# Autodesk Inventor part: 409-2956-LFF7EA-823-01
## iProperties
Created: 2010-11
Part Number: 409-2956-LFF7EA-823-01
Material: 3/8" OD TUBE - SS
Document SubType Name: Modeling
Designer: S. Boerckel
Engineer: Steve Boerckel
Mass: 468.349 g
Surface Area: 1014.84 cm^2
Volume: 57.9639 cm^3
Density: 8.08 g/cm^3
Description: PRESSURE DIFF TUBE
Length: 75.039 in
Author: S. Boerckel
Revision Number: 0
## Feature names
1. Sweep3
